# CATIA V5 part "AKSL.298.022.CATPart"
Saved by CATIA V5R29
Part number: АКСЛ.298.022
Definition: Уголок
Publications: "Грань по длине шипа", "Грань по ширине шипа"
Material "Steel": density 7860 kg/m3, Young's modulus 2e+11 Pa, Poisson ratio 0.266, thermal expansion 1.17e-05 1/K
Bounding box of the stored display mesh (mm): x -149 to 149, y -52 to 51, z -52 to 51
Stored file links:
  Z:\ООО Аксель\Соединения бруса\Соединения бруса\Соединения из листа\АКСЛ.298.020 (Дуо)\AKSL.298.022.CATPart
  Z:\ООО Аксель\Соединения бруса\Соединения бруса\Соединения из листа\АКСЛ.298.020 (Дуо)\AKSL.298.020.CATProduct
  Z:\ООО Аксель\Соединения бруса\Соединения бруса\Соединения из листа\АКСЛ.298.020 (Дуо)\AKSL.298.020.Skelet.CATPart
  Z:\#Catalog_GosNIIAS\Holes&Pockets\Part\Соединение шип-паз\Ship-Paz.CATPart
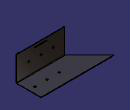
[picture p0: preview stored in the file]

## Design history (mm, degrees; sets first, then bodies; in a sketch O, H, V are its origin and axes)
External parameters (linked from other documents)
  `External.S металла` = 2 mm
  `External.R гиба` = 1.9 mm
  `External.K factor` = 0.49
SheetMetalParameters1: Thickness 2 {= `External.S металла`}, BendRadius 1.9 {= `External.R гиба`}, KFactor 0.49 {= `External.K factor`}, ReliefRadialLength 1, ReliefAxialLength 2, MinimumBendRadius 0
Set1
  DatumSurface1: linked copy from another document
  DatumCurve1: linked copy from another document
  Plane1: linked copy from another document
  DatumCurve2: linked copy from another document
  DatumCurve3: linked copy from another document
  Plane2: linked copy from another document
Body1 (main body)
  ThickSurface1: BotOffset 0, Surface DatumSurface1, TopOffset 2 {= `External.S металла`}
  Split1: SplitPlane Plane1
  Split2: SplitPlane Plane2
  Recognize1: Recognize_BendTable SheetMetalParameters1, Recognize_ReferenceFace face of ThickSurface1, Recognize_BendDefaultRadius 1.9 {= `External.R гиба`}, KFacteur 0.49 {= SheetMetalParameters1.KFactor}
  d_Bend1: Bend_BendTable SheetMetalParameters1, Bend_Thickness 2 {= `External.S металла`}, Bend_KFactor 0.49 {= SheetMetalParameters1.KFactor}, Bend_FirstSupport face of Recognize1, Bend_SecondSupport face of Recognize1, Bend_KFactorRadius 1.9 {= d_Bend1.CylindricalBendSurf_Radius}, Bend_Deduction -3.2761 {= (d_Bend1.CylindricalBendSurf_Radius+SheetMetalParameters1.Thickness*d_Bend1.Bend_KFactor)*(PI-abs(d_Bend1.BendSurf_OpenAngle))-2*(d_Bend1.CylindricalBendSurf_Radius+SheetMetalParameters1.Thickness)*tan(min((PI-abs(d_Bend1.BendSurf_OpenAngle)),(PI/2))/2)}
  Sketch1 on face of Recognize1, origin (117.977, 19.3948, -52), H (1, 0, 0), V (0, -1, 0)
    point P1 (6.023, 19.3948)
    construction line L1 (145.4124, 19.3948) -> (-179.5876, 19.3948)
    reference projected line E1 (-216.977, 19.3948) -> (83.023, 19.3948) from DatumCurve1
    construction line L2 (31.023, 97.3386) -> (31.023, -86.6614)
    reference projected line E2 (31.023, 71.3948) -> (31.023, -30.6052) from edge [face of Recognize1 | face of Recognize1]
    distance P1 L2 = 25
    horizontal: L1 H
    coincidence: E1 L1, P1 L1, E2 L2
    vertical: L2 V
  Hole1: placed by Sketch1, at (124, 0, -52) direction (0, 0, 1), diameter 8, through (limit type 6)
  RectPattern1: of Hole1, direction 1 instances 3, spacing 50, along edge [face of Recognize1 | face of d_Bend1] reversed
  Sketch2 on face of Recognize1, origin (105.1867, -52, 15.6921), H (1, 0, 0), V (0, 0, 1)
    point P1 (-6.1867, -15.6921)
    construction line L1 (-199.6909, -15.6921) -> (176.3091, -15.6921)
    reference projected line E1 (-204.1867, -15.6921) -> (95.8133, -15.6921) from DatumCurve1
    construction line L2 (43.8133, 59.7104) -> (43.8133, -123.2896)
    reference projected line E2 (43.8133, -67.6921) -> (43.8133, 36.3079) from edge [face of Recognize1 | face of Recognize1]
    distance P1 L2 = 50
    horizontal: L1 H
    coincidence: L1 E1, P1 L1, E2 L2
    vertical: L2 V
  Hole2: placed by Sketch2, at (99, -52, 0) direction (0, 1, 0), diameter 8, through (limit type 6)
  RectPattern2: of Hole2, direction 1 instances 3, spacing 50, along edge [face of Recognize1 | face of Recognize1] reversed
  Wall1: Thickness 2 {= `External.S металла`}, Profile Sketch3, ListTangentTo face of Recognize1, OffsetValue 0
  Sketch3 on face of Recognize1, origin (-52, 0, -52), H (0, -1, 0), V (-1, 0, 0)
    reference projected line E1 (-50, -201) -> (-50, 97) from edge [face of Recognize1 | face of Recognize1]
    line L1 (-51, 87) -> (-50, 87)
    line L2 (-50, 87) -> (-50, -191)
    line L3 (-50, -191) -> (-51, -191)
    line L4 (-51, -191) -> (-51, 87)
    axis line L5 (-50, -52) -> (-51, -52)
    point P7 (-50, -52)
    point P8 (-51, -52)
    distance L2 L4 = 1
    distance L1 L3 = 278
    length E1 = 298 (reference)
    perpendicularity: L2 L1
    midpoint: P7 L2, P8 L4, P7 E1
    coincidence: L2 E1
  Set2 "Шип в центре грани"
    Extract1 "Плоскость шипа": ExtractElem face of Wall1
    Extract2 "Грань по длине шипа": ExtractElem edge of Extract1
    Extract3 "Грань по ширине шипа": ExtractElem edge of Extract1
    Sketch4 on face of Recognize1, origin (0, -52, 0), H (1, 0, 0), V (0, 0, 1)
      reference projected line E1 (-47, -48.1) -> (-47, 52) from edge [face of Recognize1 | face of Recognize1]
      line L1 (149, 52) -> (149, 51)
      line L2 (149, 51) -> (139.5, 51)
      line L3 (139.5, 51) -> (139.5, 50)
      line L4 (139.5, 50) -> (-39.5, 50)
      line L5 (-39.5, 50) -> (-39.5, 51)
      line L6 (-39.5, 51) -> (-47, 51)
      point P12 (-47, 51)
      line L7 (-47, 51) -> (-47, 52)
      line L8 (-47, 52) -> (149, 52)
      distance L8 L2 = 1
      distance L8 L4 = 2
      distance L3 L1 = 9.5
      distance L7 L5 = 7.5
      distance L8 L6 = 1
      vertical: L1 V, L3 V, L5 V, L7 V
      horizontal: L2 H, L4 H, L6 H, L8 H
      coincidence: P12 E1
  CutOut1: Direction Sketch4, EndLimit through (limit type 2), Orientation true, Profile Sketch4, StartLimit through (limit type 2), Thickness1 2, Thickness2 2
  CutOut2: Direction Sketch5, EndLimit through (limit type 2), Orientation true, Profile Sketch5, StartLimit through (limit type 2)
  Sketch5 on DatumCurve2, origin (24.9612, -50, 40), H (1, 0, 0), V (0, 0, -1)
    reference projected line E1 (0, 0) -> (0, 3) from DatumCurve3
    reference projected line E2 (0, 0) -> (50, 0) from DatumCurve2
    construction line L1 (0, 1.5) -> (25, 1.5)
    point P5 (0, 1.5)
    point P6 (25, 1.5)
    axis line L2 (25, 0) -> (25, 7.3468)
    point P7 (25, 0)
    line L3 (50.1, 3.1) -> (50.1, -0.1)
    line L4 (50.1, -0.1) -> (-0.1, -0.1)
    line L5 (-0.1, -0.1) -> (-0.1, 3.1)
    line L6 (-0.1, 3.1) -> (50.1, 3.1)
    distance L5 E1 = 0.1
    distance E2 L4 = 0.1
    midpoint: P5 E1, P7 E2
    coincidence: L2 P6
    equidistance: L3 L5 P6, L4 L6 P6
    parallelism: L1 E2, L2 E1, L6 L4, L3 L5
